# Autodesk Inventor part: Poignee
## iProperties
Created: 2011-01
Part Number: Poignee
Document SubType Name: Modeling
Designer: eric
Density: 1 g/cm^3
Mass: 40.4489 g
Surface Area: 162.892 cm^2
Volume: 40.4489 cm^3
Author: eric
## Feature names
1. Base1
